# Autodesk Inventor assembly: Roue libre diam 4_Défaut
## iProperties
Shininess: 64.0
Length Units: 11269
Angle Units: 11279
Time Units: 11290
Mass Units: 11283
Length Display Precision: 3
Angle Display Precision: 2
Compacted: True
Created: 2006-01
Part Number: Roue libre diam 4_Défaut
Document SubType Name: Assembly
Designer: riri
Density: 0.0
Volumn: 0.0
Area: 0.0
PropertySet Name: Model Information
Control State: 0
Master: False
Checked Out: False
Author: riri
